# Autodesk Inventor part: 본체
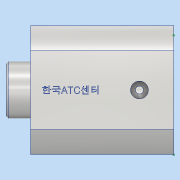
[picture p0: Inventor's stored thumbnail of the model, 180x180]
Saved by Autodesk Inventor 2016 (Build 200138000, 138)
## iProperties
Created: 2020-02
Part Number: 본체
Material: 알루미늄 6061
Document SubType Name: Modeling
Designer: MIRAE
Density: 2.7 g/cm^3
Appearance: 알루미늄 - 평지
Mass: 537.92 g
Surface Area: 342.696 cm^2
Volume: 199.23 cm^3
Author: MIRAE
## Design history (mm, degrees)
sketch "스케치1"
  geometry: L1 (7.577, 1.657)-(46.68, 1.657); L2 (59.128, 14.106)-(59.128, 53.208); L3 (46.68, 65.657)-(7.577, 65.657); L4 (-4.872, 53.208)-(-4.872, 14.106); A1 r 37.5 centre (27.128, 33.657) between (-4.872, 14.106) and (7.577, 1.657); A2 r 37.5 centre (27.128, 33.657) between (46.68, 1.657) and (59.128, 14.106); A3 r 37.5 centre (27.128, 33.657) between (59.128, 53.208) and (46.68, 65.657); A4 r 37.5 centre (27.128, 33.657) between (7.577, 65.657) and (-4.872, 53.208); 1 further point
  constraints: 8 end point, 8 point on circle, 4 centre point, 2 parallel, 1 horizontal, 1 perpendicular
extrude "돌출1" new body sketch "스케치1" distance "d4" = 71; taper "d5" = 0 deg
sketch "스케치2"
  geometry: L1 (46.68, 65.657)-(7.577, 65.657) reference; C1 r 14 at (27.128, 33.657); 1 further point
  constraints: 1 centre point
  dimensions: "d7" = 28 diameter of C1
extrude "돌출2" join sketch "스케치2" distance "d8" = 12; taper "d9" = 0 deg
sketch "스케치4"
  geometry: L1 (-46.68, 65.657)-(-7.577, 65.657) reference; C1 r 20 at (-27.128, 33.657); 2 further points
  constraints: 1 centre point, 1 coincident
extrude "돌출3" cut sketch "스케치4" distance "d18" = 62; taper "d19" = 0 deg
sketch "스케치5"
  geometry: L1 (0, 0)-(6.858, 4.757); C1 r 14 at (0, 0) reference; 2 further points
  constraints: 2 end point, 1 coincident
sketch "스케치6"
  geometry: C1 r 1.296 at (27.128, 33.657) reference; A1 r 26 centre (27.128, 33.657) between (27.128, 59.657) and (53.128, 33.657); 3 further points
  constraints: 4 point on circle, 1 centre point, 1 coincident
hole "구멍3" sketch "스케치6" at (27.128, 59.657), (53.128, 33.657), (27.128, 7.657), (1.128, 33.657) diameter "d28" = 3.242; stored, may be unused: countersink angle "d32" = 90 deg, drill point angle "d34" = 118 deg; dims "d29" = 10, "d30" = 4, "d31" = 2, "d33" = 12
sketch "스케치7"
  geometry: L1 (-27.128, 33.657)-(-4.612, 46.657); L2 (-27.128, 33.657)-(-27.128, 7.657); L3 (-27.128, 33.657)-(-49.645, 46.657); C1 r 1.296 at (-27.128, 33.657) reference; C2 r 4.458 at (-27.128, 33.657) reference; C3 r 1.621 at (-27.128, 7.657) reference; A1 r 26 centre (-27.128, 33.657) between (-4.612, 46.657) and (-49.645, 46.657); 4 further points
  constraints: 6 end point, 4 coincident, 2 point on circle, 1 centre point, 1 vertical
hole "구멍4" sketch "스케치7" at (-4.612, 46.657), (-27.128, 7.657), (-49.645, 46.657) diameter "d38" = 3.242; stored, may be unused: countersink angle "d42" = 90 deg, drill point angle "d44" = 118 deg; dims "d39" = 10, "d40" = 4, "d41" = 2, "d43" = 12
sketch "스케치9"
  geometry: C1 r 4.458 at (0, 0) reference; C2 r 2 at (0, 0); 1 further point
  constraints: 1 centre point, 1 coincident
  dimensions: "d53" = 4 diameter of C2
hole "구멍6" sketch "스케치5" diameter "d54" = 8.917; stored, may be unused: countersink angle "d58" = 90 deg, drill point angle "d60" = 118 deg; dims "d55" = 14, "d56" = 4, "d57" = 2, "d59" = 17
extrude "돌출4" cut sketch "스케치9" distance "d61" = 62; taper "d62" = 0 deg
chamfer "모따기2" distance "d66" = 1; stored, may be unused: second distance "d67" = 2, angle "d68" = 45 deg
sketch "스케치10"
  geometry: 1 further point
node "작업 평면1"
sketch "스케치11"
  geometry: L1 (33.551, -71)-(5.551, -71) reference; L2 (19.551, -71)-(19.551, -51); 2 further points
  constraints: 2 coincident, 2 end point, 1 midpoint, 1 vertical, 1 other
feature "엠보싱1" sketch "스케치11" dims "d71" = 0.5, "d72" = 0
sketch "스케치12"
  geometry: 1 further point
node "작업 평면2"
sketch "스케치13"
  geometry: L1 (0, 0)-(39.102, 0) reference; L2 (19.551, 0)-(19.551, -1.8); L3 (19.551, -1.8)-(-0.449, -1.8); L4 (-0.449, 0)-(-0.449, -62) reference; L5 (-0.449, -1.8)-(-0.931, 0); L6 (-0.449, -1.8)-(5.324, -1.8); L7 (19.551, 0)-(-0.931, 0); L8 (-12.449, 0)-(0, 0) reference; 1 further point
  constraints: 10 end point, 2 point on line, 1 horizontal, 1 midpoint, 1 perpendicular, 1 vertical
  dimensions: "d74" = 1.8 distance of L2.start L2.end
revolve "회전1" sketch "스케치13" stored, may be unused: angle "d76" = 90 deg
node "작업 평면3"
sketch "스케치14"
  geometry: L1 (39.102, 0)-(0, 0) reference; L2 (19.551, 0)-(19.551, 17); C1 r 2 at (19.551, 17); 1 further point
  constraints: 2 end point, 1 centre point, 1 coincident, 1 midpoint, 1 vertical
  dimensions: "d78" = 17 distance of L2.start L2.end; "d79" = 4 diameter of C1
extrude "돌출5" cut sketch "스케치14" stored distance "d80" = 10; taper "d81" = 0 deg
sketch "스케치15"
  geometry: L1 (0, 0)-(39.102, 0) reference; L2 (19.551, 0)-(19.551, -17); L3 (21.172, -12)-(21.172, 0) reference; L4 (19.551, 0)-(36.551, 0); 2 further points
  constraints: 4 end point, 1 coincident, 1 horizontal, 1 midpoint, 1 parallel, 1 perpendicular
  dimensions: "d82" = 17 distance of L2.start L2.end; "d83" = 90 deg angle of L2 L4 (derived)
hole "구멍7" sketch "스케치15" at (19.551, -17) diameter "d84" = 8.917; stored, may be unused: countersink angle "d88" = 90 deg, drill point angle "d90" = 118 deg; dims "d85" = 6, "d86" = 4, "d87" = 2, "d89" = 9
sketch "스케치16"
  geometry: 1 further point
node "솔리드1"
other parameters: "d69" = 90.5, "d73" = -32, "d77" = -31.25
